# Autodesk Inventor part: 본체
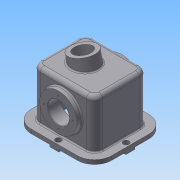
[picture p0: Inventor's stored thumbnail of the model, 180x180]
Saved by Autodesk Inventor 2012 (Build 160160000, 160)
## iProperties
Created: 2008-05
Part Number: 본체
Material: 알루미늄-6061
Document SubType Name: Modeling
Designer: net1
Density: 2.71 g/cm^3
Mass: 2881.87 g
Surface Area: 2079.03 cm^2
Volume: 1063.42 cm^3
Author: net1
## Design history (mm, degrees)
sketch "스케치1"
  geometry: L1 (0, 0)-(196, 0); L2 (196, 0)-(196, 174); L3 (196, 174)-(0, 174); L4 (0, 174)-(0, 0)
  constraints: 8 end point, 2 parallel, 1 horizontal, 1 perpendicular
  dimensions: "d0" = 196 distance of L2.end L3.end; "d1" = 174 distance of L1.end L2.end
extrude "돌출1" new body sketch "스케치1" distance "d2" = 10; taper "d3" = 0 deg
sketch "스케치2"
  geometry: L1 (196, 174)-(196, 0) reference; L2 (0, 174)-(196, 174) reference; L3 (22, 152)-(174, 152); L4 (174, 152)-(174, 22); L5 (174, 22)-(22, 22); L6 (22, 22)-(22, 152); 4 further points
  constraints: 8 end point, 4 midpoint, 2 parallel, 1 horizontal, 1 horizontal alignment, 1 perpendicular, 1 vertical alignment
  dimensions: "d4" = 152 distance of L3.start L3.end; "d5" = 130 distance of L5.end L3.start
extrude "돌출2" join sketch "스케치2" distance "d6" = 118; taper "d7" = 0 deg
sketch "스케치3"
  geometry: L1 (0, 0)-(-196, 0) reference; L2 (0, 174)-(0, 0) reference; L3 (-196, 174)-(0, 174) reference; L4 (-196, 0)-(-196, 174) reference; L5 (-109, 174)-(-87, 174); L6 (-87, 174)-(-87, 154); L7 (-87, 154)-(-109, 154); L8 (-109, 154)-(-109, 174); L9 (-196, 98)-(-176, 98); L10 (-176, 98)-(-176, 76); L11 (-176, 76)-(-196, 76); L12 (-196, 76)-(-196, 98); L13 (-109, 0)-(-87, 0); L14 (-87, 0)-(-87, 20); L15 (-87, 20)-(-109, 20); L16 (-109, 20)-(-109, 0); L17 (0, 98)-(-20, 98); L18 (-20, 98)-(-20, 76); L19 (-20, 76)-(0, 76); L20 (0, 76)-(0, 98)
  constraints: 32 end point, 8 parallel, 6 equal length, 4 horizontal, 4 perpendicular, 4 point on line, 1 horizontal alignment, 1 vertical alignment
  dimensions: "d10" = 109 distance between parallel lines of L2 L16; "d11" = 98 distance between parallel lines of L3 L11; "d12" = 22 distance of L9.end L10.end; "d13" = 20 distance of L9.start L9.end
extrude "돌출3" join sketch "스케치3" distance "d14" = 5; taper "d15" = 0 deg
fillet "모깎기3" dims "d108" = 10
fillet "모깎기4" dims "d109" = 20
node "작업 평면1"
node "작업 평면2"
node "작업 평면3"
hole "구멍5" diameter "d85" = 9; stored, may be unused: countersink angle "d89" = 90 deg, drill point angle "d91" = 118 deg; dims "d83" = 10, "d84" = 98, "d86" = 9, "d87" = 14, "d88" = 8.6, "d90" = 16
hole "구멍6" diameter "d97" = 9; stored, may be unused: countersink angle "d101" = 90 deg, drill point angle "d103" = 118 deg; dims "d95" = 10, "d96" = 87, "d98" = 9, "d99" = 14, "d100" = 8.6, "d102" = 16
fillet "모깎기2" dims "d107" = 42
node "작업 평면5"
sketch "스케치12"
  geometry: L1 (-45, 133)-(67, 133) reference; L2 (-55, 133)-(-45, 133) reference; L3 (-65, 15)-(-65, 123) reference; L4 (67, 133)-(77, 133) reference; L5 (87, 123)-(87, 15) reference; L6 (0, 5)-(-45, 5) reference; L7 (-45, 5)-(-87, 5) reference; L8 (67, 5)-(22, 5) reference; L9 (109, 5)-(67, 5) reference; L10 (0, 5)-(22, 5) reference; L11 (-55, 5)-(-55, 123); L12 (-55, 123)-(-45, 123); L13 (-45, 123)-(67, 123); L14 (67, 123)-(77, 123); L15 (77, 123)-(77, 5); L16 (109, 15)-(109, 5) reference; L17 (-87, 5)-(-87, 15) reference; A1 r 10 centre (-55, 123) between (-55, 133) and (-65, 123) reference; A2 r 10 centre (77, 123) between (87, 123) and (77, 133) reference
  constraints: 10 end point, 2 parallel, 2 point on line, 12 other
  dimensions: "d110" = 10 distance between parallel lines of L13 L1; "d111" = 20 distance from line of L13.end L5; "d112" = 132 distance from line of L12.end L5; "d113" = 32 distance between parallel lines of L16 L15; "d114" = 32 distance between parallel lines of L17 L11
extrude "돌출8" cut sketch "스케치12" stored distance "d115" = 110; taper "d116" = 0 deg
node "작업 평면6"
sketch "스케치13"
  geometry: L1 (-5, -44)-(-123, -44) reference; L2 (-123, 66)-(-5, 66) reference; L3 (-73, -44)-(-73, 66); L4 (-5, -34)-(-5, -76) reference; L5 (-118.5, -44)-(-108.5, -34); L6 (-108.5, -34)-(-73, -34); L7 (-118.5, 66)-(-108.5, 56); L8 (-108.5, 56)-(-73, 56)
  constraints: 10 end point, 6 point on line, 3 perpendicular, 2 vertical alignment
  dimensions: "d117" = 68 distance between parallel lines of L4 L3; "d118" = 10 distance between parallel lines of L6 L1; "d119" = 10 distance between parallel lines of L2 L8; "d120" = 71 diameter of L7.end L3; "d121" = 91 diameter of L7.start L3
revolve "회전2" sketch "스케치13" stored, may be unused: angle "d122" = 90 deg
sketch "스케치14"
  geometry: L1 (-34.5, 73)-(11, 73); L2 (11, 73)-(-6.88, 157.121); 1 further point
  constraints: 4 end point, 1 horizontal, 1 horizontal alignment, 1 other
  dimensions: "d123" = 78 deg angle of L1 L2; "d124" = 86 distance of L1.end L2.end
node "작업 평면7"
sketch "스케치15"
  geometry: L1 (45, -52.083)-(-45, -52.083) reference; C1 r 31 at (0, 0); 2 further points
  constraints: 1 centre point, 1 midpoint, 1 vertical alignment
  dimensions: "d125" = 62 diameter of C1; "d126" = 52.08304 distance from line of L1 C1.centre
extrude "돌출9" join sketch "스케치15" stored distance "d127" = 110; taper "d128" = 0 deg
hole "구멍7" diameter "d131" = 30; stored, may be unused: countersink angle "d135" = 90 deg, drill point angle "d137" = 118 deg; dims "d129" = 10, "d130" = 10, "d132" = 9, "d133" = 42, "d134" = 25, "d136" = 16
sketch "스케치16"
  geometry: L1 (67, -10)-(112, -10) reference; L2 (45, -15)-(67, -15) reference; C1 r 45.5 at (56, 58); 2 further points
  constraints: 1 centre point, 1 midpoint, 1 vertical alignment
  dimensions: "d138" = 68 distance from line of L1 C1.centre; "d139" = 91 diameter of C1
extrude "돌출10" join sketch "스케치16" distance "d140" = 12; taper "d141" = 0 deg
sketch "스케치17"
  geometry: L1 (67, 15)-(45, 15) reference; L2 (45, 10)-(0, 10) reference; C1 r 45.5 at (56, -58); 2 further points
  constraints: 1 centre point, 1 midpoint, 1 vertical alignment
  dimensions: "d142" = 68 distance from line of L2 C1.centre; "d143" = 91 diameter of C1
extrude "돌출11" join sketch "스케치17" distance "d144" = 12; taper "d145" = 0 deg
hole "구멍8" diameter "d148" = 52; stored, may be unused: countersink angle "d152" = 90 deg, drill point angle "d154" = 118 deg; dims "d146" = 10, "d147" = 10, "d149" = 9, "d150" = 42, "d151" = 25, "d153" = 16
sketch "스케치18" dims "d155" = 70
  geometry: C1 r 26 at (0, 0) reference; C2 r 45.5 at (0, 0) reference; 3 further points
  constraints: 2 vertical alignment, 1 coincident, 2 other
hole "구멍9" sketch "스케치18" at (0, 35) diameter "d156" = 3.242; stored, may be unused: countersink angle "d160" = 90 deg, drill point angle "d162" = 118 deg; dims "d157" = 13, "d158" = 42, "d159" = 25, "d161" = 16
sketch "스케치19"
  geometry: C1 r 1.621 at (0, -35) reference; 1 further point
hole "구멍10" sketch "스케치19" at (0, -35) diameter "d166" = 3.242; stored, may be unused: countersink angle "d170" = 90 deg, drill point angle "d172" = 118 deg; dims "d167" = 13, "d168" = 42, "d169" = 25, "d171" = 16
fillet "모깎기5" dims "d176" = 10
fillet "모깎기6" dims "d177" = 3
fillet "모깎기7" dims "d178" = 3
chamfer "모따기1" distance "d179" = 1; stored, may be unused: second distance "d180" = 2, angle "d181" = 45 deg
fillet "모깎기8" dims "d182" = 0.3
fillet "모깎기9" dims "d183" = 3
sketch "스케치20"
  geometry: L1 (-118, 90)-(-118, 56) reference; L2 (-123, 56)-(-123, 34) reference; 3 further points
  constraints: 1 horizontal alignment, 1 midpoint, 1 other
  dimensions: "d184" = 92 distance from line of L1 point (-26, 45)
feature "엠보싱1" sketch "스케치20" dims "d185" = 1, "d186" = 0
node "솔리드1"
pattern_linear "직사각형 패턴1" dims "d94" = 154
pattern_linear "직사각형 패턴2" dims "d106" = 176
pattern_circular "원형 패턴3" dims angle "d164" = 360 deg
pattern_circular "원형 패턴4" dims angle "d174" = 360 deg
node "투영된 루프1"
